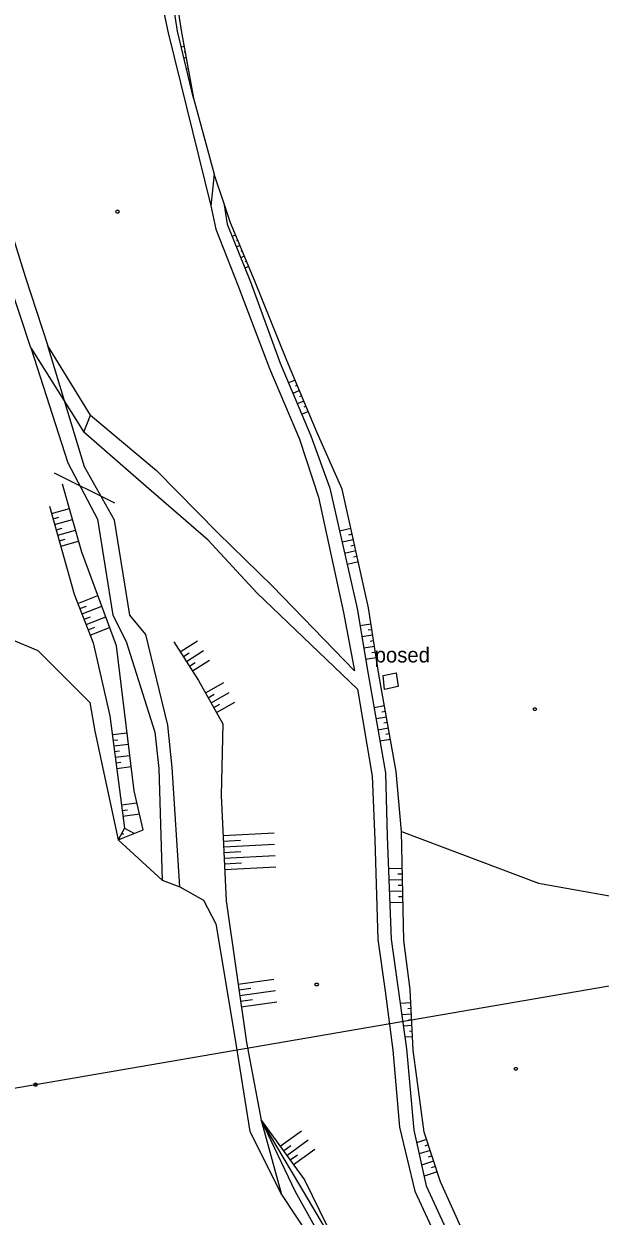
# Model space of a CAD drawing. Extents: x -664960 to -662754, y -993849 to -991145.
# Drawn here: x -663797.2 to -663675.5, y -992772.1 to -992520.3 of the extents above; entities that cross this region are included whole.
import ezdxf

# ---------------------------------------------------------------- set-up
doc = ezdxf.new("R2010")
doc.units = 0
for name, color, linetype in [('Vrstva 13', 7, 'Continuous'), ('Vrstva 2', 7, 'Continuous'), ('Vrstva 21', 7, 'Continuous'), ('Vrstva 27', 7, 'Continuous'), ('Vrstva 28', 7, 'Continuous'), ('Vrstva 37', 7, 'Continuous'), ('Vrstva 57', 7, 'Continuous'), ('Vrstva 63', 7, 'Continuous')]:
    doc.layers.add(name, color=color, linetype=linetype)

msp = doc.modelspace()

# ---------------------------------------------------------------- linework, layer by layer
at = {"layer": 'Vrstva 13'}
for points in [[(-663777.273, -992559.688), (-663777.093, -992559.988), (-663777.273, -992560.288), (-663777.633, -992560.288), (-663777.813, -992559.988), (-663777.633, -992559.688), (-663777.273, -992559.688)], [(-663689.146, -992664.751), (-663688.966, -992665.051), (-663689.146, -992665.351), (-663689.506, -992665.351), (-663689.686, -992665.051), (-663689.506, -992664.751), (-663689.146, -992664.751)], [(-663735.199, -992722.9), (-663735.019, -992723.2), (-663735.199, -992723.5), (-663735.559, -992723.5), (-663735.739, -992723.2), (-663735.559, -992722.9), (-663735.199, -992722.9)], [(-663693.159, -992740.729), (-663692.979, -992741.029), (-663693.159, -992741.329), (-663693.519, -992741.329), (-663693.699, -992741.029), (-663693.519, -992740.729), (-663693.159, -992740.729)]]:
    msp.add_lwpolyline(points, dxfattribs=at)
at = {"layer": 'Vrstva 2'}
for points in [[(-663811.376, -992535.259), (-663806.877, -992539.453), (-663805.276, -992545.936), (-663799.951, -992563.888), (-663796.892, -992573.713), (-663792.13, -992588.328)], [(-663795.743, -992588.769), (-663800.513, -992574.269), (-663803.535, -992567.523), (-663809.382, -992546.179), (-663810.722, -992541.564), (-663814.719, -992536.433)], [(-663795.743, -992588.769), (-663787.93, -992613.03), (-663781.66, -992624.94), (-663778.42, -992645.22), (-663775.59, -992650.74), (-663769.52, -992669.92), (-663768.7, -992677.61), (-663767.99, -992701.17)], [(-663764.28, -992702.55), (-663765.92, -992677.38), (-663766.82, -992668.41), (-663771.47, -992649.31), (-663774.85, -992645.23), (-663778.04, -992625.18), (-663784.41, -992613.92), (-663792.13, -992588.328)]]:
    msp.add_lwpolyline(points, dxfattribs=at)
at = {"layer": 'Vrstva 21'}
msp.add_lwpolyline([(-663721.34, -992657.92), (-663718.59, -992657.41), (-663718.16, -992660.27), (-663721.09, -992660.89), (-663721.34, -992657.92)], dxfattribs=at)
at = {"layer": 'Vrstva 27'}
for p, q in [((-663795.743, -992588.769), (-663784.52, -992606.57)), ((-663783.14, -992602.99), (-663792.13, -992588.328))]:
    msp.add_line(p, q, dxfattribs=at)
for points in [[(-663757.02, -992552.09), (-663757.75, -992558.77), (-663756.7, -992563.68), (-663752.05, -992575.51), (-663745.36, -992593.12), (-663739.02, -992608.05), (-663735.01, -992620.3), (-663729.73, -992644.67), (-663727.424, -992656.952)], [(-663726.74, -992660.813), (-663748.03, -992640.5), (-663758.27, -992629.39), (-663771.38, -992618.03), (-663784.52, -992606.57), (-663783.14, -992602.99), (-663769.23, -992614.67), (-663756.25, -992627.82), (-663744.69, -992639.07), (-663727.424, -992656.952)], [(-663726.74, -992660.813), (-663723.67, -992679.24), (-663723.11, -992692.67), (-663722.5, -992713.74), (-663720.93, -992724.62), (-663719.3, -992737.1), (-663717.9, -992753.37), (-663714.66, -992766.84), (-663709.82, -992777.33), (-663705.52, -992784.48), (-663691.77, -992801.04), (-663685.85, -992812.35), (-663682.13, -992822.13), (-663679.74, -992832.36), (-663677.04, -992847.56), (-663676.66, -992855.3)], [(-663678.13, -992862.88), (-663681.7, -992854.33), (-663685.06, -992851.05), (-663701.06, -992827.46), (-663711.05, -992809.58), (-663720.61, -992795.62), (-663729.99, -992780.72), (-663738.95, -992765.58), (-663747.07, -992751.83), (-663740.03, -992766.8), (-663733.81, -992777.91), (-663722.21, -992796.34), (-663712.91, -992810.62), (-663703.5, -992828.18), (-663686.52, -992852.99), (-663683.22, -992857.58), (-663679.79, -992866.29)]]:
    msp.add_lwpolyline(points, dxfattribs=at)
at = {"layer": 'Vrstva 28'}
msp.add_line((-663790.81, -992615.18), (-663778.06, -992621.48), dxfattribs=at)
at = {"layer": 'Vrstva 37'}
msp.add_lwpolyline([(-663794.57, -992744.05), (-663794.39, -992744.35), (-663794.57, -992744.65), (-663794.93, -992744.65), (-663795.11, -992744.35), (-663794.93, -992744.05), (-663794.57, -992744.05)], dxfattribs=at)
at = {"layer": 'Vrstva 57'}
msp.add_lwpolyline([(-663970.58, -992774.57), (-663947.81, -992770.51), (-663896.715, -992761.596), (-663794.75, -992744.35), (-663665.051, -992722.016)], dxfattribs=at)
at = {"layer": 'Vrstva 63'}
for p, q in [((-663763.376, -992525.118), (-663763.967, -992525.225)), ((-663762.951, -992527.48), (-663763.414, -992527.564)), ((-663763.163, -992526.299), (-663763.339, -992526.331)), ((-663762.738, -992528.661), (-663762.871, -992528.685)), ((-663762.525, -992529.842), (-663762.861, -992529.903)), ((-663762.313, -992531.023), (-663762.403, -992531.04)), ((-663762.1, -992532.204), (-663762.308, -992532.242)), ((-663761.41, -992536.04), (-663757.02, -992552.09)), ((-663755, -992558.13), (-663757.02, -992552.09)), ((-663752.494, -992564.952), (-663753.251, -992565.266)), ((-663751.574, -992567.169), (-663752.347, -992567.489)), ((-663752.034, -992566.06), (-663752.289, -992566.166)), ((-663750.655, -992569.386), (-663751.444, -992569.713)), ((-663751.115, -992568.277), (-663751.375, -992568.385)), ((-663750.196, -992570.494), (-663750.461, -992570.604)), ((-663749.736, -992571.603), (-663750.54, -992571.936)), ((-663739.953, -992595.572), (-663741.343, -992596.158)), ((-663739.021, -992597.783), (-663740.416, -992598.372)), ((-663739.487, -992596.677), (-663739.951, -992596.873)), ((-663738.088, -992599.995), (-663739.49, -992600.586)), ((-663738.554, -992598.889), (-663739.02, -992599.085)), ((-663737.155, -992602.206), (-663738.563, -992602.8)), ((-663737.622, -992601.1), (-663738.089, -992601.297)), ((-663791.366, -992623.732), (-663787.596, -992622.665)), ((-663791.04, -992624.887), (-663789.784, -992624.532)), ((-663790.713, -992626.042), (-663786.944, -992624.975)), ((-663790.386, -992627.196), (-663789.131, -992626.841)), ((-663790.059, -992628.351), (-663786.292, -992627.285)), ((-663728.145, -992626.939), (-663730.557, -992627.477)), ((-663727.884, -992628.11), (-663728.686, -992628.289)), ((-663789.732, -992629.506), (-663788.478, -992629.151)), ((-663789.406, -992630.66), (-663785.639, -992629.594)), ((-663727.623, -992629.282), (-663730.027, -992629.818)), ((-663727.361, -992630.453), (-663728.161, -992630.631)), ((-663727.1, -992631.624), (-663729.497, -992632.158)), ((-663726.839, -992632.795), (-663727.636, -992632.973)), ((-663726.578, -992633.967), (-663728.967, -992634.499)), ((-663785.786, -992642.715), (-663781.59, -992641.084)), ((-663785.351, -992643.834), (-663783.96, -992643.293)), ((-663784.917, -992644.952), (-663780.757, -992643.335)), ((-663784.482, -992646.07), (-663783.103, -992645.534)), ((-663784.047, -992647.189), (-663779.923, -992645.586)), ((-663783.612, -992648.307), (-663782.245, -992647.776)), ((-663783.177, -992649.426), (-663779.09, -992647.837)), ((-663723.897, -992647.087), (-663726.247, -992647.445)), ((-663723.716, -992648.274), (-663724.493, -992648.392)), ((-663764.176, -992652.942), (-663760.558, -992650.647)), ((-663723.536, -992649.46), (-663725.848, -992649.812)), ((-663723.355, -992650.646), (-663724.119, -992650.762)), ((-663763.534, -992653.956), (-663762.329, -992653.191)), ((-663762.891, -992654.969), (-663759.272, -992652.673)), ((-663723.175, -992651.833), (-663725.449, -992652.179)), ((-663722.994, -992653.019), (-663723.745, -992653.133)), ((-663762.248, -992655.982), (-663761.043, -992655.218)), ((-663761.605, -992656.995), (-663757.986, -992654.7)), ((-663722.813, -992654.205), (-663725.05, -992654.546)), ((-663758.868, -992661.606), (-663755.007, -992659.434)), ((-663758.28, -992662.652), (-663756.994, -992661.929)), ((-663757.691, -992663.698), (-663753.831, -992661.526)), ((-663756.515, -992665.79), (-663752.654, -992663.618)), ((-663757.103, -992664.744), (-663755.817, -992664.021)), ((-663721.091, -992664.367), (-663723.276, -992664.757)), ((-663720.88, -992665.548), (-663721.608, -992665.678)), ((-663720.669, -992666.729), (-663722.859, -992667.12)), ((-663720.458, -992667.911), (-663721.188, -992668.041)), ((-663778.516, -992670.447), (-663775.417, -992670.049)), ((-663720.247, -992669.092), (-663722.443, -992669.484)), ((-663720.036, -992670.273), (-663720.768, -992670.404)), ((-663778.364, -992671.637), (-663777.334, -992671.505)), ((-663778.211, -992672.828), (-663775.125, -992672.431)), ((-663719.825, -992671.454), (-663722.027, -992671.848)), ((-663778.058, -992674.018), (-663777.032, -992673.886)), ((-663777.905, -992675.208), (-663774.833, -992674.813)), ((-663777.752, -992676.398), (-663776.731, -992676.267)), ((-663777.599, -992677.589), (-663774.541, -992677.196)), ((-663776.614, -992685.258), (-663773.342, -992684.838)), ((-663776.461, -992686.448), (-663775.333, -992686.303)), ((-663776.308, -992687.639), (-663772.807, -992687.189)), ((-663776.537, -992691.253), (-663776.132, -992691.465)), ((-663775.98, -992690.19), (-663773.863, -992691.299)), ((-663755.13, -992691.708), (-663744.37, -992691.194)), ((-663777.094, -992692.316), (-663776.777, -992692.482)), ((-663755.072, -992692.907), (-663751.489, -992692.735)), ((-663755.015, -992694.105), (-663744.255, -992693.591)), ((-663754.958, -992695.304), (-663751.375, -992695.133)), ((-663754.9, -992696.503), (-663744.14, -992695.988)), ((-663754.843, -992697.701), (-663751.26, -992697.53)), ((-663754.786, -992698.9), (-663744.026, -992698.386)), ((-663717.315, -992698.692), (-663720.243, -992698.75)), ((-663717.267, -992701.091), (-663720.152, -992701.149)), ((-663717.291, -992699.891), (-663718.259, -992699.911)), ((-663717.219, -992703.491), (-663720.062, -992703.548)), ((-663717.243, -992702.291), (-663718.196, -992702.31)), ((-663717.171, -992705.89), (-663719.971, -992705.946)), ((-663717.195, -992704.691), (-663718.134, -992704.709)), ((-663751.966, -992723.171), (-663744.447, -992722.105)), ((-663751.798, -992724.359), (-663749.294, -992724.004)), ((-663751.629, -992725.547), (-663744.11, -992724.481)), ((-663751.461, -992726.736), (-663748.957, -992726.381)), ((-663751.293, -992727.924), (-663743.773, -992726.858)), ((-663715.521, -992727.09), (-663717.766, -992727.207)), ((-663715.458, -992728.289), (-663716.171, -992728.326)), ((-663715.395, -992729.487), (-663717.429, -992729.593)), ((-663715.333, -992730.685), (-663715.975, -992730.719)), ((-663715.27, -992731.884), (-663717.093, -992731.979)), ((-663715.145, -992734.28), (-663716.756, -992734.365)), ((-663715.208, -992733.082), (-663715.779, -992733.112)), ((-663743.064, -992757.346), (-663738.588, -992754.096)), ((-663741.654, -992759.288), (-663737.178, -992756.038)), ((-663712.195, -992755.959), (-663714.295, -992756.652)), ((-663742.359, -992758.317), (-663740.868, -992757.235)), ((-663740.949, -992760.259), (-663739.458, -992759.177)), ((-663740.244, -992761.23), (-663735.768, -992757.98)), ((-663711.443, -992758.238), (-663713.763, -992759.004)), ((-663711.819, -992757.098), (-663712.555, -992757.341)), ((-663711.067, -992759.377), (-663711.876, -992759.645)), ((-663710.691, -992760.517), (-663713.23, -992761.355)), ((-663710.314, -992761.656), (-663711.197, -992761.948)), ((-663709.938, -992762.796), (-663712.698, -992763.707))]:
    msp.add_line(p, q, dxfattribs=at)
for points in [[(-663767.32, -992406.44), (-663772.11, -992416.97), (-663779.13, -992443.7), (-663779.2, -992452.89), (-663770.4, -992472.65), (-663768.14, -992480.5), (-663769.87, -992507.43), (-663766.72, -992522.21), (-663757.75, -992558.77)], [(-663765.27, -992480.47), (-663764.81, -992486.16), (-663766.1, -992507.93), (-663763.98, -992521.76), (-663761.41, -992536.04), (-663764.76, -992521.87), (-663766.95, -992507.77), (-663765.73, -992486.01), (-663765.27, -992480.47)], [(-663703.64, -992777.35), (-663709.26, -992764.85), (-663712.71, -992754.4), (-663715, -992737.06), (-663715.67, -992724.23), (-663717.01, -992713.91), (-663717.47, -992690.93), (-663718.62, -992678.2), (-663722.28, -992657.71), (-663724.42, -992643.65), (-663730.01, -992618.57), (-663735.26, -992606.7), (-663741.7, -992591.43), (-663748.46, -992574.68), (-663753.56, -992562.38), (-663755, -992558.13), (-663754.31, -992562.66), (-663749.36, -992574.84), (-663743.1, -992591.96), (-663736.65, -992607.37), (-663732.62, -992618.36), (-663726.86, -992643.81), (-663724.52, -992657.69), (-663720.85, -992678.53), (-663720.5, -992691.95), (-663719.68, -992713.64), (-663716.41, -992736.82), (-663714.9, -992753.98), (-663712.24, -992765.73), (-663707.68, -992775.63)], [(-663845.399, -992595.963), (-663837.25, -992598.9), (-663830.11, -992610.6), (-663824.56, -992621.02), (-663821.39, -992636.04), (-663813.77, -992644.39), (-663803.86, -992648.63), (-663794.22, -992652.7), (-663783.25, -992663.64), (-663782.22, -992669.72), (-663777.29, -992692.69), (-663767.99, -992701.17), (-663764.28, -992702.55), (-663759.28, -992705.4), (-663756.65, -992710.39), (-663752.63, -992734.41), (-663749.52, -992754.25), (-663742.84, -992767.59)], [(-663772.04, -992690.56), (-663773.91, -992682.34), (-663777.67, -992651.67), (-663784.98, -992631.93), (-663789.04, -992617.55)], [(-663791.8, -992622.2), (-663786.55, -992640.75), (-663782.55, -992651.04), (-663779.03, -992666.45), (-663775.98, -992690.19), (-663777.29, -992692.69), (-663772.04, -992690.56)], [(-663765.51, -992650.84), (-663760.34, -992658.99), (-663755.17, -992668.18), (-663755.53, -992683.33), (-663754.47, -992705.51), (-663750.22, -992735.49)], [(-663717.47, -992690.93), (-663688.56, -992701.81), (-663665.72, -992705.89), (-663663.12, -992709.42), (-663663.27, -992721.2), (-663665.23, -992727.21), (-663670.19, -992746.8), (-663672.76, -992769.22), (-663672.43, -992781.22), (-663666.45, -992787.76)], [(-663750.22, -992735.49), (-663747.07, -992751.83), (-663742.84, -992767.59), (-663734.45, -992780.25), (-663723.96, -992796.72), (-663714.2, -992812.77)], [(-663747.07, -992751.83), (-663737.92, -992764.43), (-663729.99, -992780.72), (-663719.82, -992794.84), (-663709.62, -992809.4), (-663694.99, -992836.16), (-663685.06, -992851.05)]]:
    msp.add_lwpolyline(points, dxfattribs=at)

# ---------------------------------------------------------------- texts
msp.add_text('posed', height=3.2, dxfattribs=at).set_placement((-663723.14, -992655.201))

doc.saveas('drawing.dxf')
